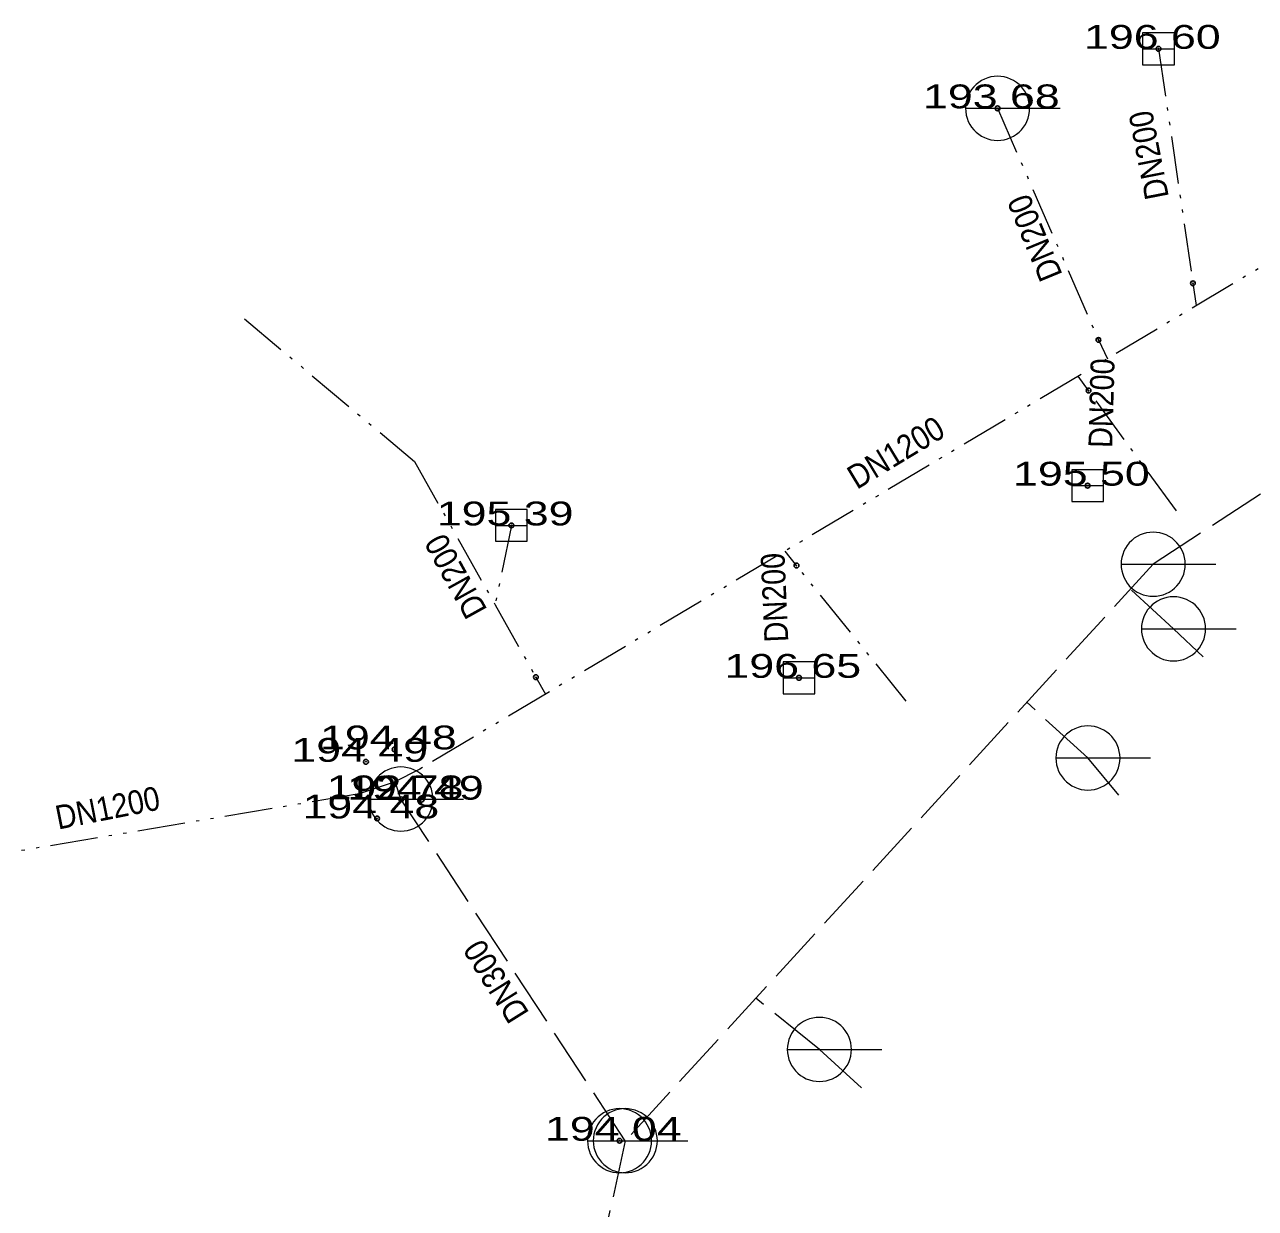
# Model space of a CAD drawing. Extents: x -688177 to -687620, y -1056713 to -1056287.
# Drawn here: x -688008.91 to -687970.23, y -1056547.55 to -1056510.34 of the extents above; entities that cross this region are included whole.
import ezdxf
from ezdxf.enums import TextEntityAlignment as Align

# ---------------------------------------------------------------- set-up
doc = ezdxf.new("R2010")
doc.units = 0
doc.header["$LTSCALE"] = 0.3
doc.header["$PDMODE"] = 32
doc.header["$PDSIZE"] = 0.15
for name, pattern in [('DASH_DOUBLE_DOT', [9.2, 5, -1.2, 0.3, -1.2, 0.3, -1.2]), ('DOTTED', [1.5, 0.3, -1.2]), ('LONG_DASHED', [7.5, 6, -1.5])]:
    doc.linetypes.add(name, pattern=pattern)
for name, color, linetype in [('1', 7, 'Continuous'), ('16', 7, 'Continuous'), ('18', 7, 'Continuous'), ('19', 7, 'Continuous'), ('3', 7, 'Continuous')]:
    doc.layers.add(name, color=color, linetype=linetype)
for name, color, linetype, lineweight in [('10', 7, 'Continuous', 13), ('12', 7, 'Continuous', 13), ('46', 7, 'DOTTED', 13), ('50', 7, 'LONG_DASHED', 13), ('51', 7, 'DASH_DOUBLE_DOT', 13)]:
    doc.layers.add(name, color=color, linetype=linetype, lineweight=lineweight)

msp = doc.modelspace()

# ---------------------------------------------------------------- linework, layer by layer
at = {"layer": '1'}
for p in [(-687973.27, -1056511.1), (-687978.33, -1056512.97), (-687972.19, -1056518.47), (-687975.16, -1056520.25), (-687975.47, -1056521.84), (-687975.5, -1056524.83), (-687993.61, -1056526.08), (-687984.65, -1056527.34), (-687992.84, -1056530.85), (-687984.57, -1056530.87), (-687997.28, -1056533.12), (-687998.18, -1056533.51), (-687997.07, -1056534.69), (-687996.43, -1056534.7), (-687997.83, -1056535.29), (-687990.21, -1056545.42)]:
    msp.add_point(p, dxfattribs=at)
at = {"layer": '10'}
for p, q in [((-687973.77, -1056511.1), (-687972.77, -1056511.1)), ((-687976, -1056524.83), (-687975, -1056524.83)), ((-687994.11, -1056526.08), (-687993.11, -1056526.08)), ((-687985.07, -1056530.87), (-687984.07, -1056530.87))]:
    msp.add_line(p, q, dxfattribs=at)
for points in [[(-687973.77, -1056511.6), (-687972.77, -1056511.6), (-687972.77, -1056510.6), (-687973.77, -1056510.6)], [(-687976, -1056525.33), (-687975, -1056525.33), (-687975, -1056524.33), (-687976, -1056524.33)], [(-687994.11, -1056526.58), (-687993.11, -1056526.58), (-687993.11, -1056525.58), (-687994.11, -1056525.58)], [(-687985.07, -1056531.37), (-687984.07, -1056531.37), (-687984.07, -1056530.37), (-687985.07, -1056530.37)]]:
    msp.add_lwpolyline(points, close=True, dxfattribs=at)
at = {"layer": '12'}
for p, q in [((-687979.338, -1056512.97), (-687976.362, -1056512.97)), ((-687974.448, -1056527.3), (-687971.472, -1056527.3)), ((-687973.808, -1056529.33), (-687970.832, -1056529.33)), ((-687976.498, -1056533.39), (-687973.522, -1056533.39)), ((-687998.088, -1056534.68), (-687995.112, -1056534.68)), ((-687984.938, -1056542.55), (-687981.962, -1056542.55)), ((-687991.218, -1056545.42), (-687988.242, -1056545.42)), ((-687991.038, -1056545.42), (-687988.062, -1056545.42))]:
    msp.add_line(p, q, dxfattribs=at)
for points in [[(-687978.33, -1056511.962), (-687978.435, -1056511.968), (-687978.539, -1056511.984), (-687978.641, -1056512.012), (-687978.74, -1056512.05), (-687978.834, -1056512.097), (-687978.922, -1056512.155), (-687979.004, -1056512.221), (-687979.079, -1056512.296), (-687979.145, -1056512.378), (-687979.203, -1056512.466), (-687979.25, -1056512.56), (-687979.288, -1056512.659), (-687979.316, -1056512.761), (-687979.332, -1056512.865), (-687979.338, -1056512.97), (-687979.332, -1056513.075), (-687979.316, -1056513.18), (-687979.288, -1056513.282), (-687979.25, -1056513.38), (-687979.203, -1056513.474), (-687979.145, -1056513.563), (-687979.079, -1056513.645), (-687979.004, -1056513.719), (-687978.922, -1056513.785), (-687978.834, -1056513.843), (-687978.74, -1056513.891), (-687978.641, -1056513.929), (-687978.539, -1056513.956), (-687978.435, -1056513.972), (-687978.33, -1056513.978), (-687978.225, -1056513.972), (-687978.12, -1056513.956), (-687978.018, -1056513.929), (-687977.92, -1056513.891), (-687977.826, -1056513.843), (-687977.737, -1056513.785), (-687977.655, -1056513.719), (-687977.581, -1056513.645), (-687977.515, -1056513.563), (-687977.457, -1056513.474), (-687977.409, -1056513.38), (-687977.371, -1056513.282), (-687977.344, -1056513.18), (-687977.328, -1056513.075), (-687977.322, -1056512.97), (-687977.328, -1056512.865), (-687977.344, -1056512.761), (-687977.371, -1056512.659), (-687977.409, -1056512.56), (-687977.457, -1056512.466), (-687977.515, -1056512.378), (-687977.581, -1056512.296), (-687977.655, -1056512.221), (-687977.737, -1056512.155), (-687977.826, -1056512.097), (-687977.92, -1056512.05), (-687978.018, -1056512.012), (-687978.12, -1056511.984), (-687978.225, -1056511.968)], [(-687973.44, -1056526.292), (-687973.545, -1056526.298), (-687973.649, -1056526.314), (-687973.751, -1056526.342), (-687973.85, -1056526.38), (-687973.944, -1056526.427), (-687974.032, -1056526.485), (-687974.114, -1056526.551), (-687974.189, -1056526.626), (-687974.255, -1056526.708), (-687974.313, -1056526.796), (-687974.36, -1056526.89), (-687974.398, -1056526.989), (-687974.426, -1056527.091), (-687974.442, -1056527.195), (-687974.448, -1056527.3), (-687974.442, -1056527.405), (-687974.426, -1056527.51), (-687974.398, -1056527.612), (-687974.36, -1056527.71), (-687974.313, -1056527.804), (-687974.255, -1056527.893), (-687974.189, -1056527.975), (-687974.114, -1056528.049), (-687974.032, -1056528.115), (-687973.944, -1056528.173), (-687973.85, -1056528.221), (-687973.751, -1056528.259), (-687973.649, -1056528.286), (-687973.545, -1056528.302), (-687973.44, -1056528.308), (-687973.335, -1056528.302), (-687973.23, -1056528.286), (-687973.128, -1056528.259), (-687973.03, -1056528.221), (-687972.936, -1056528.173), (-687972.847, -1056528.115), (-687972.765, -1056528.049), (-687972.691, -1056527.975), (-687972.625, -1056527.893), (-687972.567, -1056527.804), (-687972.519, -1056527.71), (-687972.481, -1056527.612), (-687972.454, -1056527.51), (-687972.438, -1056527.405), (-687972.432, -1056527.3), (-687972.438, -1056527.195), (-687972.454, -1056527.091), (-687972.481, -1056526.989), (-687972.519, -1056526.89), (-687972.567, -1056526.796), (-687972.625, -1056526.708), (-687972.691, -1056526.626), (-687972.765, -1056526.551), (-687972.847, -1056526.485), (-687972.936, -1056526.427), (-687973.03, -1056526.38), (-687973.128, -1056526.342), (-687973.23, -1056526.314), (-687973.335, -1056526.298)], [(-687972.8, -1056528.322), (-687972.905, -1056528.328), (-687973.009, -1056528.344), (-687973.111, -1056528.372), (-687973.21, -1056528.41), (-687973.304, -1056528.457), (-687973.392, -1056528.515), (-687973.474, -1056528.581), (-687973.549, -1056528.656), (-687973.615, -1056528.738), (-687973.673, -1056528.826), (-687973.72, -1056528.92), (-687973.758, -1056529.019), (-687973.786, -1056529.121), (-687973.802, -1056529.225), (-687973.808, -1056529.33), (-687973.802, -1056529.435), (-687973.786, -1056529.54), (-687973.758, -1056529.642), (-687973.72, -1056529.74), (-687973.673, -1056529.834), (-687973.615, -1056529.923), (-687973.549, -1056530.005), (-687973.474, -1056530.079), (-687973.392, -1056530.145), (-687973.304, -1056530.203), (-687973.21, -1056530.251), (-687973.111, -1056530.289), (-687973.009, -1056530.316), (-687972.905, -1056530.332), (-687972.8, -1056530.338), (-687972.695, -1056530.332), (-687972.59, -1056530.316), (-687972.488, -1056530.289), (-687972.39, -1056530.251), (-687972.296, -1056530.203), (-687972.207, -1056530.145), (-687972.125, -1056530.079), (-687972.051, -1056530.005), (-687971.985, -1056529.923), (-687971.927, -1056529.834), (-687971.879, -1056529.74), (-687971.841, -1056529.642), (-687971.814, -1056529.54), (-687971.798, -1056529.435), (-687971.792, -1056529.33), (-687971.798, -1056529.225), (-687971.814, -1056529.121), (-687971.841, -1056529.019), (-687971.879, -1056528.92), (-687971.927, -1056528.826), (-687971.985, -1056528.738), (-687972.051, -1056528.656), (-687972.125, -1056528.581), (-687972.207, -1056528.515), (-687972.296, -1056528.457), (-687972.39, -1056528.41), (-687972.488, -1056528.372), (-687972.59, -1056528.344), (-687972.695, -1056528.328)], [(-687975.49, -1056532.382), (-687975.595, -1056532.388), (-687975.699, -1056532.404), (-687975.801, -1056532.432), (-687975.9, -1056532.47), (-687975.994, -1056532.517), (-687976.082, -1056532.575), (-687976.164, -1056532.641), (-687976.239, -1056532.716), (-687976.305, -1056532.798), (-687976.363, -1056532.886), (-687976.41, -1056532.98), (-687976.448, -1056533.079), (-687976.476, -1056533.181), (-687976.492, -1056533.285), (-687976.498, -1056533.39), (-687976.492, -1056533.495), (-687976.476, -1056533.6), (-687976.448, -1056533.702), (-687976.41, -1056533.8), (-687976.363, -1056533.894), (-687976.305, -1056533.983), (-687976.239, -1056534.065), (-687976.164, -1056534.139), (-687976.082, -1056534.205), (-687975.994, -1056534.263), (-687975.9, -1056534.311), (-687975.801, -1056534.349), (-687975.699, -1056534.376), (-687975.595, -1056534.392), (-687975.49, -1056534.398), (-687975.385, -1056534.392), (-687975.28, -1056534.376), (-687975.178, -1056534.349), (-687975.08, -1056534.311), (-687974.986, -1056534.263), (-687974.897, -1056534.205), (-687974.815, -1056534.139), (-687974.741, -1056534.065), (-687974.675, -1056533.983), (-687974.617, -1056533.894), (-687974.569, -1056533.8), (-687974.531, -1056533.702), (-687974.504, -1056533.6), (-687974.488, -1056533.495), (-687974.482, -1056533.39), (-687974.488, -1056533.285), (-687974.504, -1056533.181), (-687974.531, -1056533.079), (-687974.569, -1056532.98), (-687974.617, -1056532.886), (-687974.675, -1056532.798), (-687974.741, -1056532.716), (-687974.815, -1056532.641), (-687974.897, -1056532.575), (-687974.986, -1056532.517), (-687975.08, -1056532.47), (-687975.178, -1056532.432), (-687975.28, -1056532.404), (-687975.385, -1056532.388)], [(-687997.08, -1056533.672), (-687997.185, -1056533.678), (-687997.289, -1056533.694), (-687997.391, -1056533.722), (-687997.49, -1056533.76), (-687997.584, -1056533.807), (-687997.672, -1056533.865), (-687997.754, -1056533.931), (-687997.829, -1056534.006), (-687997.895, -1056534.088), (-687997.953, -1056534.176), (-687998, -1056534.27), (-687998.038, -1056534.369), (-687998.066, -1056534.471), (-687998.082, -1056534.575), (-687998.088, -1056534.68), (-687998.082, -1056534.785), (-687998.066, -1056534.89), (-687998.038, -1056534.992), (-687998, -1056535.09), (-687997.953, -1056535.184), (-687997.895, -1056535.273), (-687997.829, -1056535.355), (-687997.754, -1056535.429), (-687997.672, -1056535.495), (-687997.584, -1056535.553), (-687997.49, -1056535.601), (-687997.391, -1056535.639), (-687997.289, -1056535.666), (-687997.185, -1056535.682), (-687997.08, -1056535.688), (-687996.975, -1056535.682), (-687996.87, -1056535.666), (-687996.768, -1056535.639), (-687996.67, -1056535.601), (-687996.576, -1056535.553), (-687996.487, -1056535.495), (-687996.405, -1056535.429), (-687996.331, -1056535.355), (-687996.265, -1056535.273), (-687996.207, -1056535.184), (-687996.159, -1056535.09), (-687996.121, -1056534.992), (-687996.094, -1056534.89), (-687996.078, -1056534.785), (-687996.072, -1056534.68), (-687996.078, -1056534.575), (-687996.094, -1056534.471), (-687996.121, -1056534.369), (-687996.159, -1056534.27), (-687996.207, -1056534.176), (-687996.265, -1056534.088), (-687996.331, -1056534.006), (-687996.405, -1056533.931), (-687996.487, -1056533.865), (-687996.576, -1056533.807), (-687996.67, -1056533.76), (-687996.768, -1056533.722), (-687996.87, -1056533.694), (-687996.975, -1056533.678)], [(-687983.93, -1056541.542), (-687984.035, -1056541.548), (-687984.139, -1056541.564), (-687984.241, -1056541.592), (-687984.34, -1056541.63), (-687984.434, -1056541.677), (-687984.522, -1056541.735), (-687984.604, -1056541.801), (-687984.679, -1056541.876), (-687984.745, -1056541.958), (-687984.803, -1056542.046), (-687984.85, -1056542.14), (-687984.888, -1056542.239), (-687984.916, -1056542.341), (-687984.932, -1056542.445), (-687984.938, -1056542.55), (-687984.932, -1056542.655), (-687984.916, -1056542.76), (-687984.888, -1056542.862), (-687984.85, -1056542.96), (-687984.803, -1056543.054), (-687984.745, -1056543.143), (-687984.679, -1056543.225), (-687984.604, -1056543.299), (-687984.522, -1056543.365), (-687984.434, -1056543.423), (-687984.34, -1056543.471), (-687984.241, -1056543.509), (-687984.139, -1056543.536), (-687984.035, -1056543.552), (-687983.93, -1056543.558), (-687983.825, -1056543.552), (-687983.72, -1056543.536), (-687983.618, -1056543.509), (-687983.52, -1056543.471), (-687983.426, -1056543.423), (-687983.337, -1056543.365), (-687983.255, -1056543.299), (-687983.181, -1056543.225), (-687983.115, -1056543.143), (-687983.057, -1056543.054), (-687983.009, -1056542.96), (-687982.971, -1056542.862), (-687982.944, -1056542.76), (-687982.928, -1056542.655), (-687982.922, -1056542.55), (-687982.928, -1056542.445), (-687982.944, -1056542.341), (-687982.971, -1056542.239), (-687983.009, -1056542.14), (-687983.057, -1056542.046), (-687983.115, -1056541.958), (-687983.181, -1056541.876), (-687983.255, -1056541.801), (-687983.337, -1056541.735), (-687983.426, -1056541.677), (-687983.52, -1056541.63), (-687983.618, -1056541.592), (-687983.72, -1056541.564), (-687983.825, -1056541.548)], [(-687990.21, -1056544.412), (-687990.315, -1056544.418), (-687990.419, -1056544.434), (-687990.521, -1056544.462), (-687990.62, -1056544.5), (-687990.714, -1056544.547), (-687990.802, -1056544.605), (-687990.884, -1056544.671), (-687990.959, -1056544.746), (-687991.025, -1056544.828), (-687991.083, -1056544.916), (-687991.13, -1056545.01), (-687991.168, -1056545.109), (-687991.196, -1056545.211), (-687991.212, -1056545.315), (-687991.218, -1056545.42), (-687991.212, -1056545.525), (-687991.196, -1056545.63), (-687991.168, -1056545.732), (-687991.13, -1056545.83), (-687991.083, -1056545.924), (-687991.025, -1056546.013), (-687990.959, -1056546.095), (-687990.884, -1056546.169), (-687990.802, -1056546.235), (-687990.714, -1056546.293), (-687990.62, -1056546.341), (-687990.521, -1056546.379), (-687990.419, -1056546.406), (-687990.315, -1056546.422), (-687990.21, -1056546.428), (-687990.105, -1056546.422), (-687990, -1056546.406), (-687989.898, -1056546.379), (-687989.8, -1056546.341), (-687989.706, -1056546.293), (-687989.617, -1056546.235), (-687989.535, -1056546.169), (-687989.461, -1056546.095), (-687989.395, -1056546.013), (-687989.337, -1056545.924), (-687989.289, -1056545.83), (-687989.251, -1056545.732), (-687989.224, -1056545.63), (-687989.208, -1056545.525), (-687989.202, -1056545.42), (-687989.208, -1056545.315), (-687989.224, -1056545.211), (-687989.251, -1056545.109), (-687989.289, -1056545.01), (-687989.337, -1056544.916), (-687989.395, -1056544.828), (-687989.461, -1056544.746), (-687989.535, -1056544.671), (-687989.617, -1056544.605), (-687989.706, -1056544.547), (-687989.8, -1056544.5), (-687989.898, -1056544.462), (-687990, -1056544.434), (-687990.105, -1056544.418)], [(-687990.03, -1056544.412), (-687990.135, -1056544.418), (-687990.239, -1056544.434), (-687990.341, -1056544.462), (-687990.44, -1056544.5), (-687990.534, -1056544.547), (-687990.622, -1056544.605), (-687990.704, -1056544.671), (-687990.779, -1056544.746), (-687990.845, -1056544.828), (-687990.903, -1056544.916), (-687990.95, -1056545.01), (-687990.988, -1056545.109), (-687991.016, -1056545.211), (-687991.032, -1056545.315), (-687991.038, -1056545.42), (-687991.032, -1056545.525), (-687991.016, -1056545.63), (-687990.988, -1056545.732), (-687990.95, -1056545.83), (-687990.903, -1056545.924), (-687990.845, -1056546.013), (-687990.779, -1056546.095), (-687990.704, -1056546.169), (-687990.622, -1056546.235), (-687990.534, -1056546.293), (-687990.44, -1056546.341), (-687990.341, -1056546.379), (-687990.239, -1056546.406), (-687990.135, -1056546.422), (-687990.03, -1056546.428), (-687989.925, -1056546.422), (-687989.82, -1056546.406), (-687989.718, -1056546.379), (-687989.62, -1056546.341), (-687989.526, -1056546.293), (-687989.437, -1056546.235), (-687989.355, -1056546.169), (-687989.281, -1056546.095), (-687989.215, -1056546.013), (-687989.157, -1056545.924), (-687989.109, -1056545.83), (-687989.071, -1056545.732), (-687989.044, -1056545.63), (-687989.028, -1056545.525), (-687989.022, -1056545.42), (-687989.028, -1056545.315), (-687989.044, -1056545.211), (-687989.071, -1056545.109), (-687989.109, -1056545.01), (-687989.157, -1056544.916), (-687989.215, -1056544.828), (-687989.281, -1056544.746), (-687989.355, -1056544.671), (-687989.437, -1056544.605), (-687989.526, -1056544.547), (-687989.62, -1056544.5), (-687989.718, -1056544.462), (-687989.82, -1056544.434), (-687989.925, -1056544.418)]]:
    msp.add_lwpolyline(points, close=True, dxfattribs=at)
at = {"layer": '46', "linetype": 'DASH_DOUBLE_DOT'}
for points in [[(-687963.07, -1056513.7), (-687963.77, -1056514.21), (-687996.49, -1056533.74), (-687997.29, -1056534.15)], [(-687997.29, -1056534.15), (-687998.39, -1056534.52), (-688015.55, -1056537.4), (-688017.82, -1056537.41)]]:
    msp.add_lwpolyline(points, dxfattribs=at)
at = {"layer": '50'}
for points in [[(-687956.31, -1056519.9), (-687958.76, -1056517.72), (-687973.44, -1056527.3), (-687990.03, -1056545.42), (-687993.39, -1056560.73)], [(-687971.87, -1056530.21), (-687972.8, -1056529.33), (-687974.16, -1056528.08)], [(-687974.52, -1056534.56), (-687975.49, -1056533.39), (-687977.41, -1056531.64)], [(-687990.03, -1056545.42), (-687997.08, -1056534.68), (-687997.26, -1056534.14)], [(-687982.61, -1056543.76), (-687983.93, -1056542.55), (-687985.93, -1056540.94)]]:
    msp.add_lwpolyline(points, dxfattribs=at)
at = {"layer": '51'}
msp.add_line((-687993.61, -1056526.08), (-687994.12, -1056528.58), dxfattribs=at)
for points in [[(-687973.27, -1056511.1), (-687972.19, -1056518.47), (-687972.09, -1056519.17)], [(-687978.33, -1056512.97), (-687975.16, -1056520.25), (-687974.87, -1056520.84)], [(-688002, -1056519.59), (-687996.65, -1056524.07), (-687994.12, -1056528.58), (-687992.84, -1056530.85), (-687992.54, -1056531.38)], [(-687972.71, -1056525.62), (-687975.47, -1056521.84), (-687975.8, -1056521.39)], [(-687981.2, -1056531.6), (-687984.65, -1056527.34), (-687985.01, -1056526.89)]]:
    msp.add_lwpolyline(points, dxfattribs=at)

# ---------------------------------------------------------------- texts
at = {"layer": '16', "width": 0.9}
for rotation, p in [(101.012, (-687972.944, -1056515.752)), (88.465, (-687974.727, -1056523.65)), (118.946, (-687994.353, -1056528.729)), (92.533, (-687984.905, -1056529.736))]:
    msp.add_text('DN200', height=0.75, rotation=rotation, dxfattribs=at).set_placement(p)
at = {"layer": '18', "width": 0.9}
for rotation, p in [(31.169, (-687982.75, -1056524.965)), (11.173, (-688007.852, -1056535.642))]:
    msp.add_text('DN1200', height=0.75, rotation=rotation, dxfattribs=at).set_placement(p)
at = {"layer": '19', "width": 0.9}
for s, rotation, p in [('DN200', 112.472, (-687976.279, -1056518.2)), ('DN300', 122.04, (-687993.032, -1056541.404))]:
    msp.add_text(s, height=0.75, rotation=rotation, dxfattribs=at).set_placement(p)
at = {"layer": '3', "width": 1.4}
for s, p in [('196 60 ', (-687973.27, -1056511.1)), ('193 68 ', (-687978.33, -1056512.97)), ('195 50 ', (-687975.5, -1056524.83)), ('195 39 ', (-687993.61, -1056526.08)), ('196 65 ', (-687984.57, -1056530.87)), ('194 48 ', (-687997.28, -1056533.12)), ('194 49 ', (-687998.18, -1056533.51)), ('192 78 ', (-687997.07, -1056534.69)), ('194 49 ', (-687996.43, -1056534.7)), ('194 48 ', (-687997.83, -1056535.29)), ('194 04 ', (-687990.21, -1056545.42))]:
    msp.add_text(s, height=0.75, dxfattribs=at).set_placement(p, align=Align.CENTER)

doc.saveas('drawing.dxf')
